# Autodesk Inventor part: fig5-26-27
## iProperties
Created: 2004-05
Part Number: fig5-26-27
Document SubType Name: Modeling
Designer: CADCIM Technologies
Manufacturer: Standard
Standards Organization: Custom
Density: 1 g/cm^3
Author: CADCIM Technologies
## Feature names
1. Extrusion1
2. Fillet1
3. Extrusion2
4. Hole1
5. Fillet2
